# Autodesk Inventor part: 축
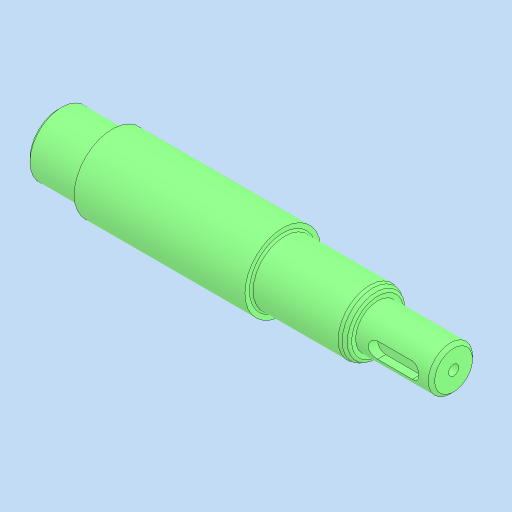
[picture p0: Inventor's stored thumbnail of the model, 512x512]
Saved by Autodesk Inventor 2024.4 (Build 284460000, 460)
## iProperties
Created: 2026-07
Part Number: 축
Material: 강철, 탄소
Document SubType Name: Modeling
Designer: home
Density: 7.85 g/cm^3
Appearance: 기본값
Author: jhkim
Sending System: Autodesk Inventor 2027
Preprocessor: ST-DEVELOPER v20.1
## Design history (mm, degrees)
feature "솔리드1"
node "솔리드2"
